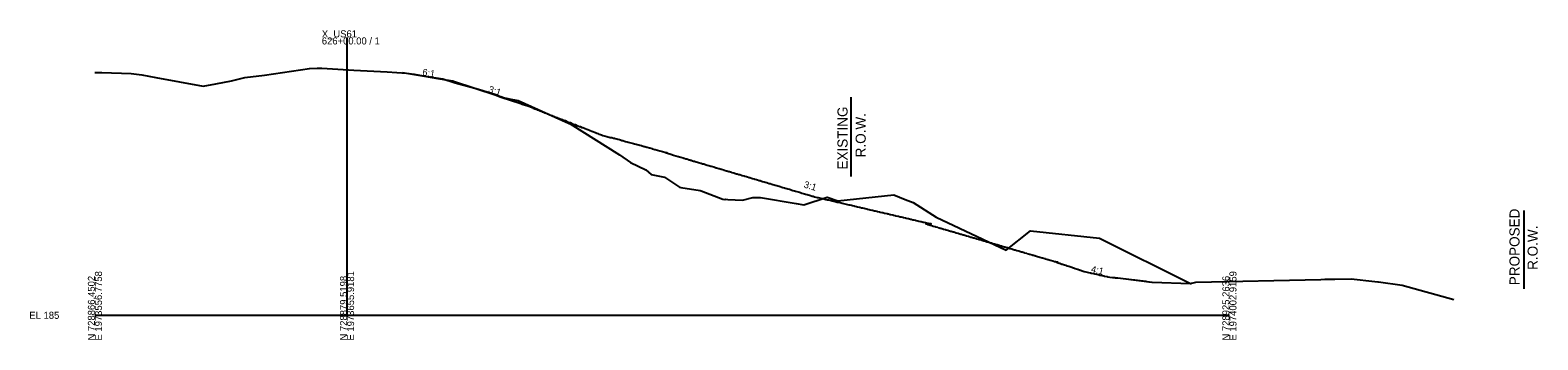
# Model space of a CAD drawing. Extents: x -26 to 630, y -39 to 9098.
# Drawn here: x -26 to 572, y 4990 to 5113 of the extents above; entities that cross this region are included whole.
import ezdxf

# ---------------------------------------------------------------- set-up
doc = ezdxf.new("R2010")
doc.units = 0
for name, color, linetype in [('CONST_DCH', 7, 'Continuous'), ('Draft_XS_Grid', 7, 'Continuous'), ('DTM_X_GROUND', 7, 'Continuous'), ('X_DTM_CONTOURS_MAJOR', 7, 'Continuous'), ('XS_CELL', 7, 'Continuous'), ('XS_P_GROUND', 7, 'Continuous'), ('XS_P_ROW', 7, 'Continuous'), ('XS_P_TX_FS_BS', 7, 'Continuous'), ('XS_X_ROW', 7, 'Continuous')]:
    doc.layers.add(name, color=color, linetype=linetype)

msp = doc.modelspace()

# ---------------------------------------------------------------- linework, layer by layer
at = {"layer": 'DTM_X_GROUND'}
msp.add_lwpolyline([(0, 5096.16), (0.28, 5096.16), (2.76, 5096.08), (14.44, 5095.69), (17.54, 5095.33), (18.61, 5095.21), (24.11, 5094.19), (42.9, 5090.66), (48.01, 5091.65), (54.15, 5092.84), (59.51, 5094.06), (67.21, 5095.06), (85.15, 5097.69), (88.1, 5097.82), (88.78, 5097.85), (89.97, 5097.78), (102.71, 5097.08), (115.92, 5096.32), (123.63, 5095.89), (124.6, 5095.76), (126.63, 5095.51), (131.04, 5094.67), (137.94, 5093.58), (142.95, 5092.05), (150.74, 5089.95), (152.15, 5089.5), (159.38, 5087.2), (159.86, 5087.03), (160.14, 5086.93), (161.46, 5086.46), (162.08, 5086.23), (162.9, 5085.94), (163.06, 5085.89), (165.68, 5085.46), (167.94, 5085.06), (187.88, 5076.03), (188.05, 5075.94), (188.14, 5075.9), (188.51, 5075.72), (208.13, 5063.48), (212.39, 5060.48), (218.56, 5057.64), (220.6, 5055.78), (225.93, 5054.65), (231.88, 5050.7), (232.45, 5050.54), (240.02, 5049.36), (240.44, 5049.3), (249.1, 5045.99), (249.86, 5045.84), (250.08, 5045.95), (250.98, 5045.88), (256.86, 5045.52), (260.99, 5046.68), (264.05, 5046.59), (278.14, 5044.31), (281.14, 5043.68), (290.45, 5046.72), (294.72, 5045.25), (316.95, 5047.69), (321.39, 5045.88), (324.51, 5044.68), (333.69, 5038.88), (361.44, 5025.81), (371.07, 5033.45), (398.43, 5030.5), (434.53, 5012.57), (434.82, 5012.63), (434.82, 5012.63), (434.87, 5012.65), (434.92, 5012.66), (434.98, 5012.67), (435.04, 5012.69), (436.67, 5013.06), (486.32, 5014.21), (487.86, 5014.25), (489.27, 5014.28), (490.57, 5014.31), (491.77, 5014.34), (491.83, 5014.34), (498.34, 5014.49), (507.62, 5013.44), (508.82, 5013.28), (508.99, 5013.25), (509.09, 5013.24), (518.58, 5011.96), (538.99, 5006.3)], dxfattribs=at)
at = {"layer": 'XS_CELL'}
for p, q in [((100, 5000), (100, 5110)), ((0, 5000), (100, 5000)), ((100, 5000), (450, 5000))]:
    msp.add_line(p, q, dxfattribs=at)
at = {"layer": 'XS_P_GROUND'}
for points in [[(142, 5092.65), (138.55, 5093.22), (137, 5093.48), (132.36, 5094.25), (122, 5095.98)], [(160.61, 5086.44), (160.48, 5086.48), (159.45, 5086.83), (159.42, 5086.84), (159.12, 5086.94), (159.11, 5086.94), (142.27, 5092.55), (142.05, 5092.63), (142, 5092.65)], [(173.79, 5082.05), (172.12, 5082.61), (170.39, 5083.18), (169.85, 5083.36), (169.58, 5083.45), (169.42, 5083.5), (169.32, 5083.54), (169.24, 5083.56), (169.19, 5083.58), (168.59, 5083.78), (168.54, 5083.8), (161.19, 5086.25), (161.1, 5086.28), (161.02, 5086.3), (160.96, 5086.33), (160.9, 5086.34), (160.86, 5086.36), (160.82, 5086.37), (160.78, 5086.38), (160.75, 5086.4), (160.72, 5086.4), (160.61, 5086.44)], [(173.79, 5082.05), (174.47, 5081.78), (174.48, 5081.77), (175.44, 5081.4), (175.48, 5081.38), (176.42, 5081.01), (176.48, 5080.98), (177.4, 5080.62), (177.48, 5080.59), (178.38, 5080.24), (178.48, 5080.2), (179.36, 5079.85), (179.48, 5079.8), (180.34, 5079.46), (180.48, 5079.41), (181.33, 5079.07), (181.48, 5079.01), (182.31, 5078.68), (182.48, 5078.62), (183.29, 5078.3), (183.48, 5078.22), (184.28, 5077.91), (184.48, 5077.83), (184.94, 5077.65), (185.1, 5077.58), (185.48, 5077.43), (185.99, 5077.23), (186.48, 5077.04), (187.24, 5076.74), (187.48, 5076.64), (188.22, 5076.35), (188.48, 5076.25), (189.21, 5075.96), (189.49, 5075.85), (190.2, 5075.57), (190.49, 5075.46), (191.19, 5075.18), (191.49, 5075.06), (192.18, 5074.79), (192.49, 5074.67), (193.17, 5074.4), (193.49, 5074.27), (194.16, 5074.01), (194.49, 5073.88), (195.15, 5073.61), (195.49, 5073.48), (196.14, 5073.22), (196.49, 5073.09), (197.13, 5072.83), (197.49, 5072.69), (198.12, 5072.44), (198.49, 5072.3), (199.11, 5072.05), (199.49, 5071.9), (199.86, 5071.75), (200.49, 5071.51), (200.92, 5071.38), (201.49, 5071.21), (201.99, 5071.06), (202.49, 5070.92), (203.04, 5070.75), (203.49, 5070.62), (204.03, 5070.46), (204.38, 5070.36), (204.45, 5070.34), (205.04, 5070.34), (205.7, 5070.16), (206.05, 5070.06), (206.39, 5069.97), (207.05, 5069.79), (207.41, 5069.69), (208.05, 5069.52), (208.43, 5069.41), (209.06, 5069.24), (209.46, 5069.13), (210.06, 5068.97), (210.49, 5068.85), (211.06, 5068.7), (211.52, 5068.57), (212.07, 5068.42), (212.56, 5068.29), (213.07, 5068.15), (213.6, 5068.01), (214.07, 5067.88), (214.64, 5067.72), (215.08, 5067.6), (215.69, 5067.44), (216.08, 5067.33), (216.75, 5067.15), (217.08, 5067.06), (217.82, 5066.86), (218.09, 5066.78), (218.89, 5066.56), (219.09, 5066.51), (219.99, 5066.26), (220.09, 5066.24), (221, 5065.99), (221.1, 5065.96), (221.2, 5065.94), (222.1, 5065.69), (222.17, 5065.67), (223.1, 5065.42), (223.14, 5065.41), (224.11, 5065.14), (224.11, 5065.14), (224.13, 5065.14), (225.07, 5064.88), (225.11, 5064.87), (226.04, 5064.62), (226.11, 5064.6), (226.53, 5064.48), (226.94, 5064.37), (226.53, 5064.32), (226.45, 5064.31), (226.53, 5064.29), (227.45, 5064.01), (227.98, 5063.86), (228.45, 5063.72), (229.43, 5063.43), (229.45, 5063.43), (230.39, 5063.15), (230.45, 5063.13), (231.36, 5062.86), (231.45, 5062.84), (231.84, 5062.72), (232.45, 5062.54), (233.29, 5062.3), (233.45, 5062.25), (233.77, 5062.15), (234.45, 5061.95), (234.73, 5061.87), (235.45, 5061.66), (235.69, 5061.59), (235.92, 5061.52), (236.18, 5061.44), (236.45, 5061.36), (237.09, 5061.18), (237.45, 5061.07), (237.62, 5061.02), (237.77, 5060.97), (238.1, 5060.88), (238.45, 5060.77), (239.06, 5060.59), (239.45, 5060.48), (240.35, 5060.21), (240.45, 5060.18), (240.5, 5060.17), (241.06, 5060.01), (241.45, 5059.89), (241.45, 5059.89), (241.46, 5059.89), (242.45, 5059.59), (242.9, 5059.46), (243.31, 5059.34), (243.38, 5059.32), (243.45, 5059.3), (244.34, 5059.04), (244.46, 5059.01), (244.46, 5059), (245.46, 5058.71), (245.49, 5058.7), (246.46, 5058.42), (246.53, 5058.4), (247.46, 5058.12), (247.56, 5058.09), (248.46, 5057.83), (248.59, 5057.79), (249.46, 5057.53), (249.61, 5057.49), (250.46, 5057.24), (250.64, 5057.18), (251.46, 5056.94), (251.67, 5056.88), (252.46, 5056.65), (252.69, 5056.58), (253.46, 5056.35), (253.72, 5056.28), (254.46, 5056.06), (254.74, 5055.98), (255.46, 5055.76), (255.76, 5055.67), (256.46, 5055.47), (256.78, 5055.37), (257.46, 5055.17), (257.79, 5055.08), (258.46, 5054.88), (258.8, 5054.78), (259.46, 5054.59), (259.8, 5054.48), (260.46, 5054.29), (260.8, 5054.19), (261.46, 5054), (261.81, 5053.89), (262.46, 5053.7), (262.81, 5053.6), (263.46, 5053.41), (263.81, 5053.3), (264.46, 5053.11), (264.82, 5053.01), (265.46, 5052.82), (265.82, 5052.71), (266.46, 5052.52), (266.82, 5052.42), (267.46, 5052.23), (267.83, 5052.12), (268.46, 5051.93), (268.83, 5051.82), (269.46, 5051.64), (269.84, 5051.53), (270.46, 5051.34), (270.84, 5051.23), (271.46, 5051.05), (271.84, 5050.94), (272.46, 5050.76), (272.85, 5050.64), (273.46, 5050.46), (273.85, 5050.34), (274.46, 5050.17), (274.86, 5050.05), (275.46, 5049.87), (275.86, 5049.75), (276.46, 5049.58), (276.87, 5049.46), (277.46, 5049.28), (277.87, 5049.16), (278.46, 5048.99), (278.88, 5048.86), (279.46, 5048.69), (279.88, 5048.57), (280.46, 5048.4), (280.89, 5048.27), (281.46, 5048.1), (281.89, 5047.98), (282.46, 5047.81), (282.9, 5047.68), (283.46, 5047.51), (283.9, 5047.38), (284.46, 5047.22), (284.91, 5047.09), (285.46, 5046.92), (285.92, 5046.82), (286.46, 5046.69), (286.92, 5046.58), (287.46, 5046.46), (287.93, 5046.35), (288.46, 5046.23), (288.95, 5046.11), (289.46, 5045.99), (289.96, 5045.88), (290.46, 5045.76), (290.97, 5045.64), (291.46, 5045.53), (291.98, 5045.41), (292.46, 5045.3), (292.99, 5045.17), (293.46, 5045.06), (294, 5044.94), (294.46, 5044.83), (294.92, 5044.72), (295.46, 5044.6), (295.94, 5044.49), (296.46, 5044.37), (296.98, 5044.24), (297.46, 5044.13), (298.02, 5044), (298.46, 5043.9), (299.05, 5043.76), (299.46, 5043.67), (300.07, 5043.53), (300.46, 5043.43), (301.1, 5043.29), (301.46, 5043.2), (302.11, 5043.05), (302.46, 5042.97), (303.12, 5042.82), (303.46, 5042.74), (304.13, 5042.58), (304.46, 5042.5), (305.14, 5042.35), (305.46, 5042.27), (306.15, 5042.11), (306.46, 5042.04), (307.15, 5041.88), (307.46, 5041.81), (308.16, 5041.64), (308.46, 5041.57), (309.17, 5041.41), (309.46, 5041.34), (310.18, 5041.18), (310.46, 5041.11), (311.18, 5040.94), (311.46, 5040.88), (312.19, 5040.71), (312.46, 5040.64), (313.19, 5040.47), (313.46, 5040.41), (314.2, 5040.24), (314.46, 5040.18), (314.72, 5040.12), (315.46, 5039.94), (315.73, 5039.88), (316.46, 5039.71), (316.73, 5039.65), (317.46, 5039.48), (317.73, 5039.42), (318.46, 5039.25), (318.74, 5039.18), (319.46, 5039.01), (319.74, 5038.95), (320.46, 5038.78), (320.75, 5038.72), (321.46, 5038.55), (321.75, 5038.48), (322.47, 5038.32), (322.75, 5038.25), (323.47, 5038.08), (323.76, 5038.02), (324.47, 5037.85), (324.76, 5037.78), (325.47, 5037.62), (325.77, 5037.55), (326.47, 5037.39), (326.77, 5037.31), (327.47, 5037.15), (327.78, 5037.08), (328.47, 5036.92), (328.78, 5036.85), (329.47, 5036.69), (329.79, 5036.61), (330.47, 5036.46), (330.79, 5036.38), (331.47, 5036.22), (331.54, 5036.21), (331.69, 5036.17), (330.64, 5036.18), (329.57, 5036.22), (330.16, 5036.05), (330.23, 5036), (330.49, 5035.92), (331.24, 5035.7), (331.5, 5035.63), (332.26, 5035.41), (332.51, 5035.33), (333.27, 5035.11), (333.53, 5035.04), (334.29, 5034.82), (334.54, 5034.74), (335.3, 5034.52), (335.56, 5034.45), (336.31, 5034.23), (336.57, 5034.15), (337.33, 5033.93), (337.59, 5033.86), (338.34, 5033.64), (338.6, 5033.57), (339.36, 5033.35), (339.61, 5033.27), (340.37, 5033.05), (340.63, 5032.98), (341.39, 5032.76), (341.64, 5032.68), (342.4, 5032.46), (342.66, 5032.39), (343.42, 5032.17), (343.67, 5032.09), (344.43, 5031.87), (344.69, 5031.8), (345.44, 5031.58), (345.7, 5031.5), (346.46, 5031.28), (346.72, 5031.21), (347.47, 5030.99), (347.73, 5030.91), (348.49, 5030.69), (348.74, 5030.62), (349.5, 5030.4), (349.76, 5030.32), (350.52, 5030.1), (350.77, 5030.03), (351.53, 5029.81), (351.79, 5029.73), (352.55, 5029.51), (352.8, 5029.44), (353.56, 5029.22), (353.82, 5029.14), (354.57, 5028.92), (354.83, 5028.85), (355.59, 5028.63), (355.84, 5028.55), (356.6, 5028.33), (356.86, 5028.26), (357.62, 5028.04), (357.87, 5027.96), (358.63, 5027.74), (358.89, 5027.67), (359.65, 5027.45), (359.9, 5027.37), (360.66, 5027.15), (360.92, 5027.08), (361.68, 5026.86), (361.93, 5026.78), (362.69, 5026.56), (362.94, 5026.49), (363.7, 5026.27), (363.96, 5026.19), (364.72, 5025.97), (364.97, 5025.9), (365.73, 5025.68), (366.53, 5025.45), (366.75, 5025.38), (367.58, 5025.14), (367.76, 5025.09), (368.63, 5024.84), (368.78, 5024.79), (369.68, 5024.53), (369.79, 5024.5), (370.74, 5024.22), (370.81, 5024.2), (371.81, 5023.91), (371.82, 5023.91), (372, 5023.86), (372.28, 5023.78), (372.62, 5023.68), (372.84, 5023.61), (373.1, 5023.54), (373.85, 5023.32), (374.46, 5023.14), (374.86, 5023.02), (375.69, 5022.78), (375.88, 5022.73), (376.75, 5022.48), (376.89, 5022.43), (376.92, 5022.43), (376.97, 5022.41), (377.54, 5022.25), (377.91, 5022.14), (378.15, 5022.07), (378.92, 5021.84), (379.38, 5021.71), (379.94, 5021.55), (380.61, 5021.35), (380.95, 5021.25), (381.22, 5021.18), (381.89, 5020.98), (381.68, 5021), (381.59, 5021), (381.43, 5021), (381.41, 5021), (382.45, 5020.66), (382.46, 5020.65), (382.71, 5020.57), (383.52, 5020.3), (383.77, 5020.22), (384.58, 5019.95), (385.05, 5019.79), (385.63, 5019.6), (386.27, 5019.39), (386.69, 5019.25), (387.44, 5019), (387.74, 5018.9), (388.59, 5018.62), (388.8, 5018.55), (389.72, 5018.24), (389.85, 5018.2), (390.84, 5017.87), (390.91, 5017.85), (391.95, 5017.5), (391.96, 5017.5), (392.39, 5017.35), (393.02, 5017.21), (393.1, 5017.19), (394.07, 5016.97), (394.85, 5016.8), (395.13, 5016.74), (395.48, 5016.66), (396.19, 5016.5), (396.67, 5016.39), (397.24, 5016.26), (397.86, 5016.12), (398.3, 5016.02), (398.65, 5015.94), (399.35, 5015.78), (400.23, 5015.59), (400.41, 5015.55), (401.42, 5015.32), (401.46, 5015.31), (401.77, 5015.24)], [(401.77, 5015.24), (402.52, 5015.15), (402.53, 5015.15), (403.57, 5015.02), (403.6, 5015.02), (404.63, 5014.9), (404.68, 5014.89), (405.68, 5014.77), (405.76, 5014.77), (406.74, 5014.65), (406.84, 5014.64), (407.79, 5014.52), (407.92, 5014.51), (408.85, 5014.4), (409.01, 5014.38), (409.91, 5014.27), (410.1, 5014.25), (410.96, 5014.15), (411.19, 5014.12), (412.02, 5014.02), (412.3, 5013.99), (413.07, 5013.9), (413.41, 5013.86), (414.13, 5013.77), (414.53, 5013.72), (415.18, 5013.64), (415.67, 5013.59), (416.24, 5013.52), (416.82, 5013.45), (417.29, 5013.39), (418.01, 5013.31), (418.35, 5013.27), (419.23, 5013.16), (419.4, 5013.14), (434.52, 5012.57), (434.53, 5012.57)]]:
    msp.add_lwpolyline(points, dxfattribs=at)
at = {"layer": 'XS_P_ROW'}
msp.add_line((566.73, 5041.45), (566.73, 5010.44), dxfattribs=at)
at = {"layer": 'XS_X_ROW'}
msp.add_line((300, 5055), (300, 5086.36), dxfattribs=at)

# ---------------------------------------------------------------- texts
at = {"layer": 'CONST_DCH'}
for height, p in [(0.12, (291.13, 5048.91)), (0.001, (401.77, 5015.24)), (0.001, (401.77, 5015.24))]:
    msp.add_text('X', height=height, dxfattribs=at).set_placement(p)
at = {"layer": 'Draft_XS_Grid'}
msp.add_text('-', height=0.0001, dxfattribs=at).set_placement((0, 5000))
at = {"layer": 'X_DTM_CONTOURS_MAJOR'}
msp.add_text('X', height=0.12, dxfattribs=at).set_placement((290.12, 5053.58))
at = {"layer": 'XS_CELL'}
for s, p in [('X_US61', (90, 5110)), ('626+00.00 / 1', (90, 5107.2)), ('EL 185', (-26, 4998.6))]:
    msp.add_text(s, height=2.8, dxfattribs=at).set_placement(p)
for s, p in [('N 728866.4502', (0, 4990)), ('E 1973556.7758', (2.8, 4990)), ('N 728879.5198', (100, 4990)), ('E 1973655.9181', (102.8, 4990)), ('N 728925.2636', (450, 4990)), ('E 1974002.9159', (452.8, 4990))]:
    msp.add_text(s, height=2.8, rotation=90, dxfattribs=at).set_placement(p)
at = {"layer": 'XS_P_ROW'}
for s, p in [('EXISTING', (298.54, 5057.68)), ('R.O.W.', (305.74, 5062.52)), ('PROPOSED', (565.08, 5011.91)), ('R.O.W.', (572.28, 5017.98))]:
    msp.add_text(s, height=4, rotation=90, dxfattribs=at).set_placement(p)
at = {"layer": 'XS_P_TX_FS_BS'}
for s, rotation, p in [('6:1', 350.53768, (129.72, 5095)), ('3:1', 341.56506, (155.81, 5088.36)), ('3:1', 343.51411, (280.98, 5050.64)), ('4:1', 347.29217, (394.91, 5017.09))]:
    msp.add_text(s, height=2.7, rotation=rotation, dxfattribs=at).set_placement(p)

doc.saveas('drawing.dxf')
